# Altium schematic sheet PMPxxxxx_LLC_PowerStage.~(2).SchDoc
size 431 x 279 mm; Date: Not shown in title block; ApprovedBy: Not shown in title block; CheckedBy: Not shown in title block; Author: Not shown in title block; CompanyName: Not shown in title block; Engineer: Not shown in title block; Organization: Not shown in title block; Address1: Not shown in title block; Address2: Not shown in title block; Address3: Not shown in title block; Address4: Not shown in title block; DocumentNumber: 2; Revision: Use project parameter SCH_Rev; SheetNumber: 2; SheetTotal: 4; PageSetup: Record=PageOptions¦CenterHorizontal=True¦CenterVertical=True¦PrintScale=1.00¦XCorrection=1.00¦YCorrection=1.00¦PrintKind=0¦BorderSize=5000000¦LeftOffset=0¦BottomOffset=0¦Orientation=2¦PaperLength=1000¦PaperWidth=1000¦Scale=100¦PaperSource=15¦PrintQuality=600¦MediaType=1¦DitherType=10¦PaperKind=Letter¦PrintScaleMode=1
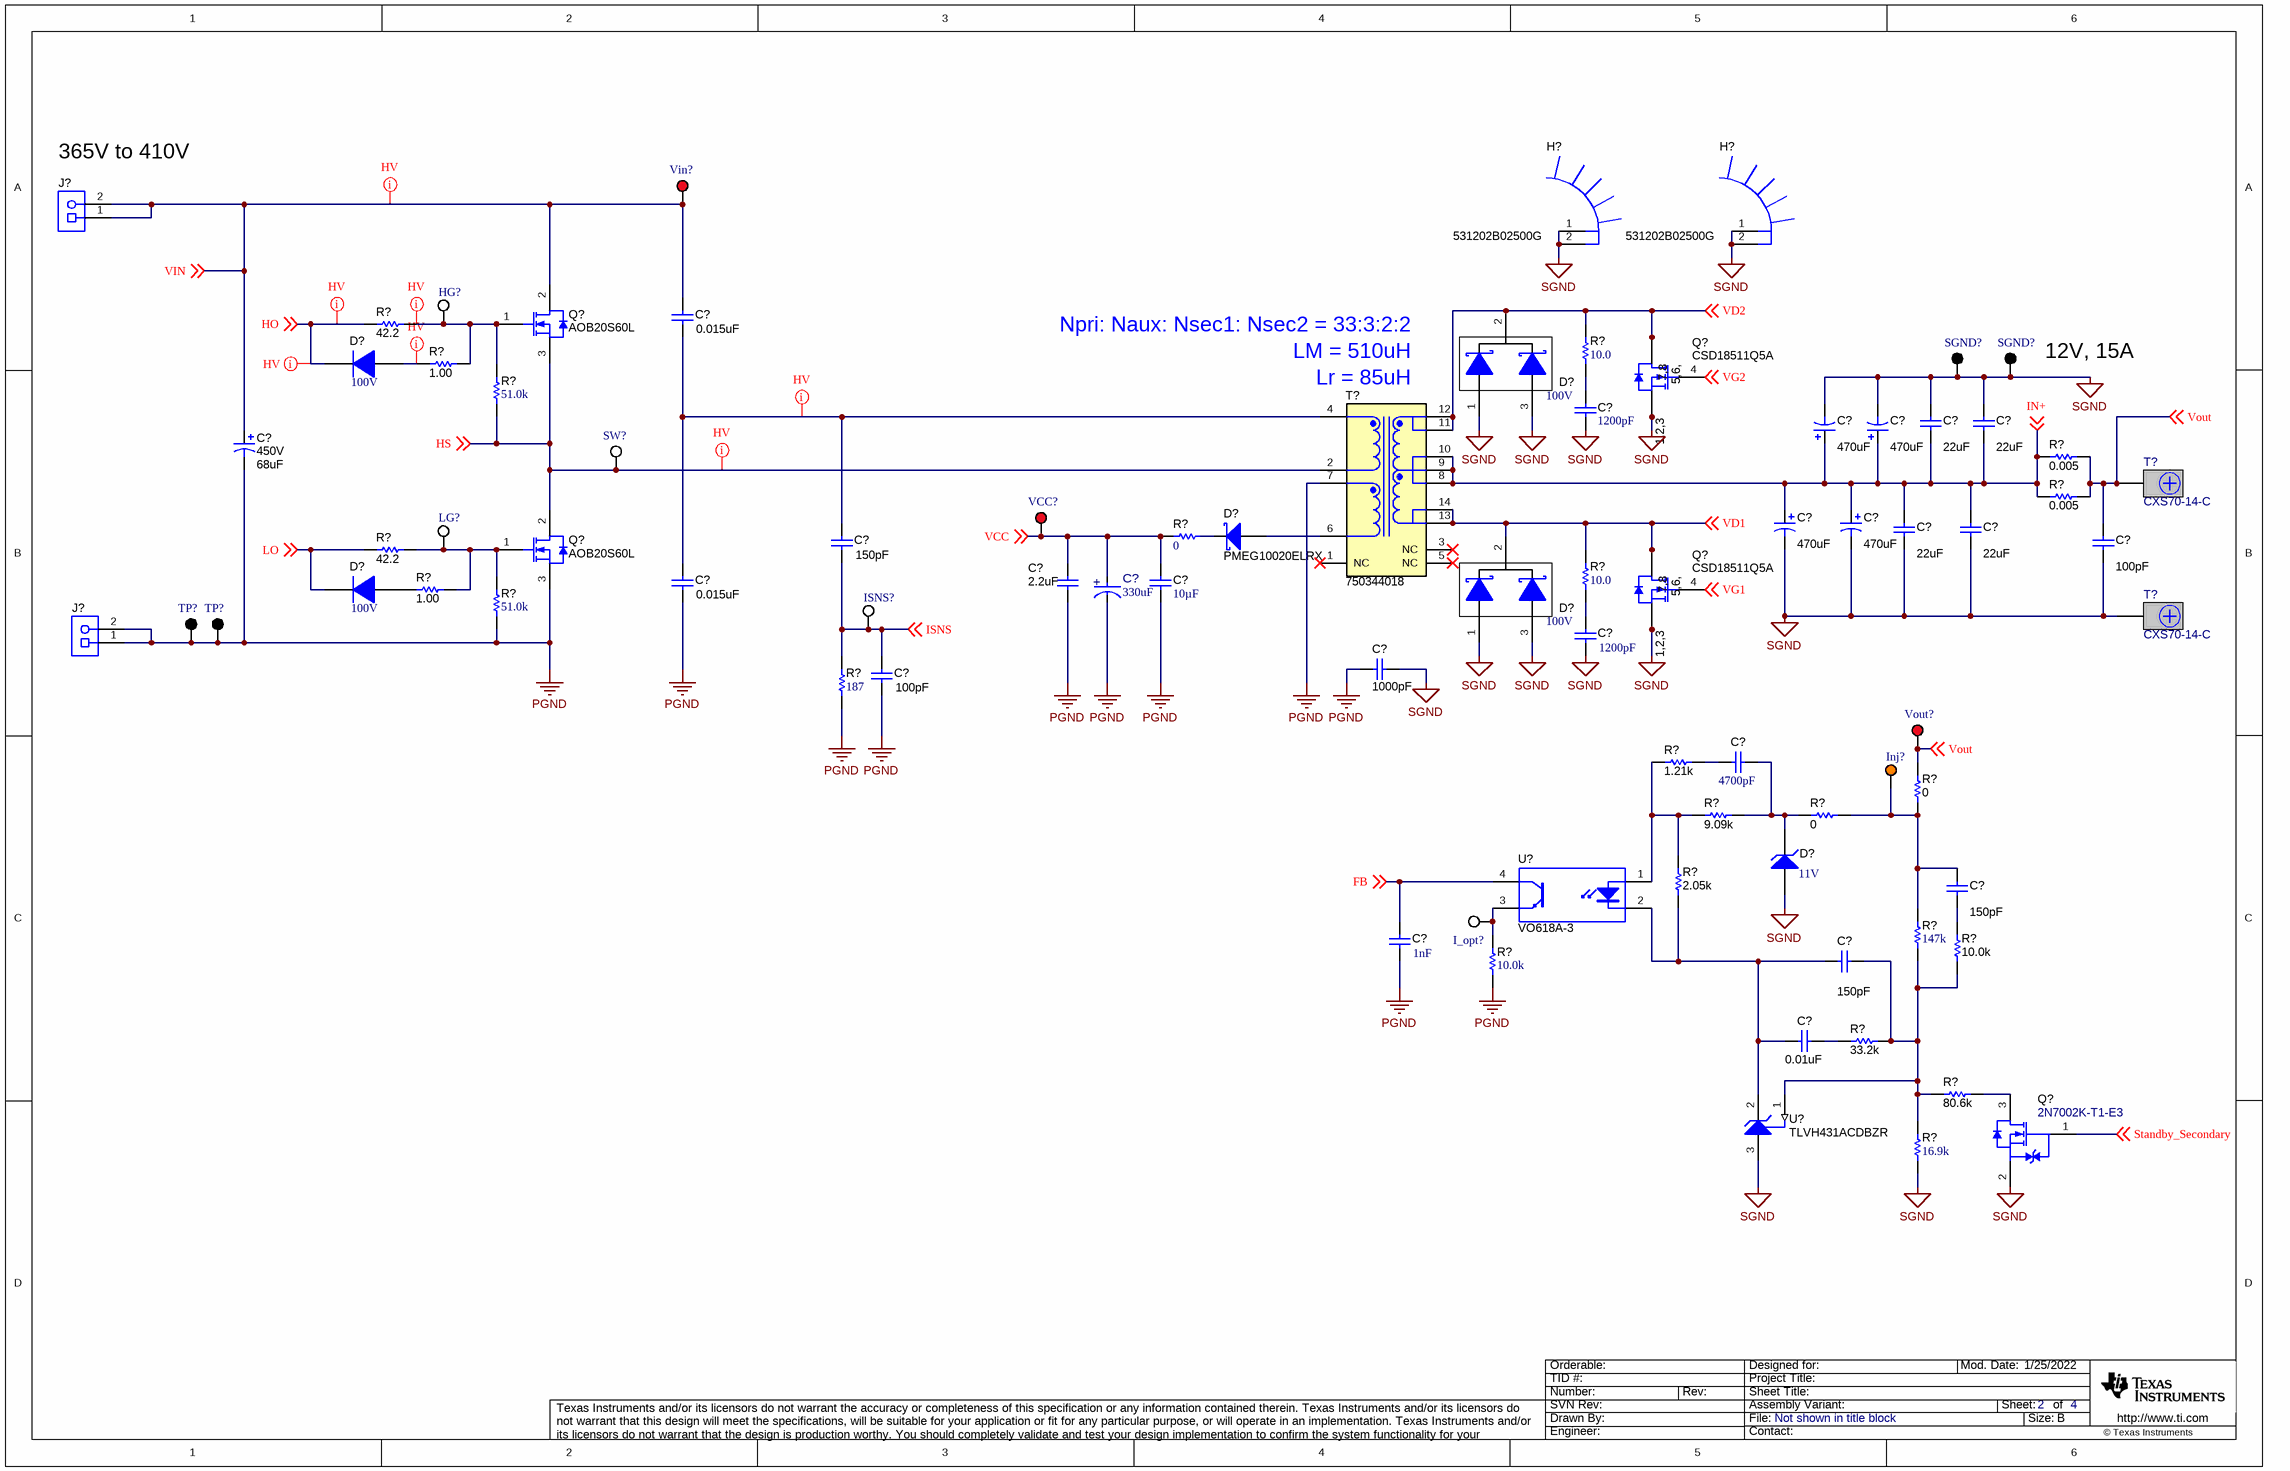
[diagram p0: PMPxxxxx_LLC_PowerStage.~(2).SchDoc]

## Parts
(Parts that share a designator on the sheet are numbered #1, #2 ... from top to bottom, then left to right.)
C?#1  ValueDisplayed: 0.015uF  [B32652_1800x700x1250]  (hidden comment: B32652A7153J000)
C?#2  ValueDisplayed: 1200pF  [0805L]  (hidden comment: GRM2165C2A122JA01D)
C?#3  ValueDisplayed: 470uF  [HW_1000x1600]  (hidden comment: UHW1V471MPD)
C?#4  ValueDisplayed: 470uF  [HW_1000x1600]  (hidden comment: UHW1V471MPD)
C?#5  ValueDisplayed: 22uF  [1206_190L]  (hidden comment: C3216X5R1E226M160AB)
C?#6  ValueDisplayed: 22uF  [1206_190L]  (hidden comment: C3216X5R1E226M160AB)
C?#7  VDC_V: 450V  ValueDisplayed: 68uF  [KXG_1800x3150]  (hidden comment: EKXG451ELL680MMN3S)
C?#8  ValueDisplayed: 470uF  [HW_1000x1600]  (hidden comment: UHW1V471MPD)
C?#9  ValueDisplayed: 470uF  [HW_1000x1600]  (hidden comment: UHW1V471MPD)
C?#10  ValueDisplayed: 22uF  [1206_190L]  (hidden comment: C3216X5R1E226M160AB)
C?#11  ValueDisplayed: 22uF  [1206_190L]  (hidden comment: C3216X5R1E226M160AB)
C?#12  ValueDisplayed: 150pF  [1206L]  (hidden comment: GRM31A5C2J151JW01D)
C?#13  ValueDisplayed: 100pF  [0603L]  (hidden comment: 06035A101FAT2A)
C?#14  ValueDisplayed: 330uF  [FP-35ZL330MEFC10X16_RADIAL-MFG]  (hidden comment: 35ZL330MEFC10X16)
C?#15  ValueDisplayed: 0.015uF  [B32652_1800x700x1250]  (hidden comment: B32652A7153J000)
C?#16  ValueDisplayed: 2.2uF  [0805L]  (hidden comment: C2012X7R1V225K085AC)
C?#17  ValueDisplayed: 10µF  [1206_180]  (hidden comment: C1206C106J3RACAUTO)
C?#18  ValueDisplayed: 1200pF  [0805L]  (hidden comment: GRM2165C2A122JA01D)
C?#19  ValueDisplayed: 1000pF  [CD45_700x600x1100]  (hidden comment: CD45-E2GA102M-NKA)
C?#20  ValueDisplayed: 100pF  [1206L]  (hidden comment: 12061A101JAT2A)
C?#21  ValueDisplayed: 4700pF  [0603L]  (hidden comment: C0603C472J1GAC7867)
C?#22  ValueDisplayed: 150pF  [0402L]  (hidden comment: 885012005062)
C?#23  Cap_F: 1nF  [1206L]  (hidden comment: 12061A102JAT2A)
C?#24  ValueDisplayed: 150pF  [0402L]  (hidden comment: 885012005062)
C?#25  ValueDisplayed: 0.01uF  [0603L]  (hidden comment: 06031C103JAT2A)
D?#1  Vr_V: 100V  [SOD-123]  (hidden comment: 1N4148W-7-F)
D?#2  Vr_V: 100V  [TO-220AB_100mil]  (hidden comment: STPS41H100CTY)
D?#3  PMEG10020ELRX  [SOD-123W]
D?#4  Vr_V: 100V  [SOD-123]  (hidden comment: 1N4148W-7-F)
D?#5  Vr_V: 100V  [TO-220AB_100mil]  (hidden comment: STPS41H100CTY)
D?#6  Vz_V: 11V  [SMA]  (hidden comment: 1SMA5926BT3G)
H?#1  531202B02500G  [531202]
H?#2  531202B02500G  [531202]
HG?  5012  [Keystone5012]  (value not drawn)
I_opt?  5012  [Keystone5012]  (value not drawn)
Inj?  5013  [Keystone5013]  (value not drawn)
ISNS?  5012  [Keystone5012]  (value not drawn)
J?#1  ED120/2DS  [On-Shore_ED120_2DS]  (value not drawn)
J?#2  ED120/2DS  [On-Shore_ED120_2DS]  (value not drawn)
LG?  5012  [Keystone5012]  (value not drawn)
Q?#1  AOB20S60L  [DDPAK]
Q?#2  CSD18511Q5A  [DQJ0008A]
Q?#3  AOB20S60L  [DDPAK]
Q?#4  CSD18511Q5A  [DQJ0008A]
Q?#5  2N7002K-T1-E3  [SOT-23L]
R?#1  ValueDisplayed: 42.2  [0603]  (hidden comment: RC0603FR-0742R2L)
R?#2  ValueDisplayed: 10.0  [1206L]  (hidden comment: RC1206FR-0710RL)
R?#3  ValueDisplayed: 1.00  [0603L]  (hidden comment: RC0603FR-071RL)
R?#4  ValueDisplayed: 51.0k  [0603L]  (hidden comment: RC0603FR-0751KL)
R?#5  ValueDisplayed: 0.005  [2010L]  (hidden comment: CSNL2010FT5L00)
R?#6  ValueDisplayed: 0.005  [2010L]  (hidden comment: CSNL2010FT5L00)
R?#7  ValueDisplayed: 0  [1206L]  (hidden comment: ERJ-8GEY0R00V)
R?#8  ValueDisplayed: 42.2  [0603L]  (hidden comment: RC0603FR-0742R2L)
R?#9  ValueDisplayed: 10.0  [1206L]  (hidden comment: RC1206FR-0710RL)
R?#10  ValueDisplayed: 1.00  [0603L]  (hidden comment: RC0603FR-071RL)
R?#11  ValueDisplayed: 51.0k  [0603L]  (hidden comment: RC0603FR-0751KL)
R?#12  ValueDisplayed: 187  [1206]  (hidden comment: RC1206FR-07187RL)
R?#13  ValueDisplayed: 1.21k  [0603L]  (hidden comment: RC0603FR-071K21L)
R?#14  ValueDisplayed: 0  [0402L]  (hidden comment: RC0402JR-070RL)
R?#15  ValueDisplayed: 9.09k  [0603L]  (hidden comment: RC0603FR-079K09L)
R?#16  ValueDisplayed: 0  [1206L]  (hidden comment: CRCW12060000Z0EAHP)
R?#17  ValueDisplayed: 2.05k  [0603L]  (hidden comment: RC0603FR-072K05L)
R?#18  ValueDisplayed: 147k  [0603L]  (hidden comment: RC0603FR-07147KL)
R?#19  ValueDisplayed: 10.0k  [0603L]  (hidden comment: ERJ-3EKF1002V)
R?#20  ValueDisplayed: 10.0k  [0402L]  (hidden comment: ERJ-2RKF1002X)
R?#21  ValueDisplayed: 33.2k  [0603L]  (hidden comment: RC0603FR-0733K2L)
R?#22  ValueDisplayed: 80.6k  [0603L]  (hidden comment: RC0603FR-0780K6L)
R?#23  ValueDisplayed: 16.9k  [0603L]  (hidden comment: RC0603FR-0716K9L)
SGND?#1  5011  [Keystone5011]  (value not drawn)
SGND?#2  5011  [Keystone5011]  (value not drawn)
SW?  5012  [Keystone5012]  (value not drawn)
T?#1  750344018  [Wurth_750344018]
T?#2  CXS70-14-C  [Panduit_CXS70-14-C]
T?#3  CXS70-14-C  [Panduit_CXS70-14-C]
TP?#1  5011  [Keystone5011]  (value not drawn)
TP?#2  5011  [Keystone5011]  (value not drawn)
U?#1  VO618A-3  [DIP-4]
U?#2  TLVH431ACDBZR  [DBZ0003A_N]
VCC?  5010  [Keystone5010]  (value not drawn)
Vin?  5010  [Keystone5010]  (value not drawn)
Vout?  5010  [Keystone5010]  (value not drawn)

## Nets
PGND: C?#7.2(-) C?#14.1(CATHODE) C?#15.2 C?#16.2 C?#17.2 C?#19.2 C?#20.2 C?#23.2 J?#2.1 J?#2.2 Q?#3.3(S) R?#11.1 R?#12.1 R?#20.1 T?#1.7 TP?#1.1 TP?#2.1
SGND: C?#2.2 C?#3.2(-) C?#4.2(-) C?#5.1 C?#6.1 C?#8.2(-) C?#9.2(-) C?#10.2 C?#11.2 C?#13.2 C?#18.2 C?#19.1 D?#2.1(A) D?#2.3(A) D?#5.1(A) D?#5.3(A) D?#6.2(A) H?#1.1 H?#1.2 H?#2.1 H?#2.2 Q?#2.1(S) Q?#2.2(S) Q?#2.3(S) Q?#4.1(S) Q?#4.2(S) Q?#4.3(S) Q?#5.2(S) R?#23.1 SGND?#1.1 SGND?#2.1 T?#3.1 U?#2.3(ANODE)
FB: C?#23.1 U?#1.4(C) ; off-sheet FB
HO: D?#1.1(K) R?#1.1 ; off-sheet HO
HS: Q?#1.3(S) Q?#3.2(D) R?#4.1 SW?.1 T?#1.2 ; off-sheet HS
IN+: C?#3.1(+) C?#4.1(+) C?#5.2 C?#6.2 C?#8.1(+) C?#9.1(+) C?#10.1 C?#11.1 R?#5.1 R?#6.1 T?#1.8 T?#1.9 T?#1.10 ; off-sheet IN+
ISNS: C?#12.2 C?#20.1 ISNS?.1 R?#12.2 ; off-sheet ISNS
LO: D?#4.1(K) R?#8.1 ; off-sheet LO
Standby_Secondary: Q?#5.1(G) ; off-sheet Standby_Secondary
VCC: C?#14.2(ANODE) C?#16.1 C?#17.1 R?#7.1 VCC?.1 ; off-sheet VCC
VD1: D?#5.2(K) Q?#4.5(D) Q?#4.6(D) Q?#4.7(D) Q?#4.8(D) Q?#4.9(D) R?#9.2 T?#1.13 T?#1.14 ; off-sheet VD1
VD2: D?#2.2(K) Q?#2.5(D) Q?#2.6(D) Q?#2.7(D) Q?#2.8(D) Q?#2.9(D) R?#2.2 T?#1.11 T?#1.12 ; off-sheet VD2
VG1: Q?#4.4(G) ; off-sheet VG1
VG2: Q?#2.4(G) ; off-sheet VG2
VIN: C?#1.1 C?#7.1(+) J?#1.1 J?#1.2 Q?#1.2(D) Vin?.1 ; off-sheet VIN
Vout: C?#13.1 R?#5.2 R?#6.2 R?#14.2 T?#2.1 Vout?.1 ; off-sheet Vout
NetC?#1_2: C?#1.2 C?#12.1 C?#15.1 T?#1.4
NetC?#2_1: C?#2.1 R?#2.1
NetC?#18_1: C?#18.1 R?#9.1
NetC?#21_1: C?#21.1 D?#6.1(K) R?#15.2 R?#16.1
NetC?#21_2: C?#21.2 R?#13.2
NetC?#22_1: C?#22.1 Inj?.1 R?#14.1 R?#16.2 R?#18.2
NetC?#22_2: C?#22.2 R?#19.2
NetC?#24_1: C?#24.1 R?#18.1 R?#19.1 R?#21.1 R?#22.1 R?#23.2 U?#2.1(REF)
NetC?#24_2: C?#24.2 C?#25.2 R?#17.1 U?#1.2(K) U?#2.2(CATHODE)
NetC?#25_1: C?#25.1 R?#21.2
NetD?#1_2: D?#1.2(A) R?#3.1
NetD?#3_1: D?#3.1(K) R?#7.2
NetD?#3_2: D?#3.2(A) T?#1.6
NetD?#4_2: D?#4.2(A) R?#10.1
NetHG?_1: HG?.1 Q?#1.1(G) R?#1.2 R?#3.2 R?#4.2
NetI_opt?_1: I_opt?.1 R?#20.2 U?#1.3(E)
NetLG?_1: LG?.1 Q?#3.1(G) R?#8.2 R?#10.2 R?#11.2
NetQ?#5_3: Q?#5.3(D) R?#22.2
NetR?#13_1: R?#13.1 R?#15.1 R?#17.2 U?#1.1(A)

Not connected (* = marked no-connect by the designer): T?#1 1(NC)* 3(NC)* 5(NC)*

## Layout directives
net class HV: HO, HS, NetC?#1_2, NetD?#1_2, NetHG?_1, VIN

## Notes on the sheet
- (near J?#1) 365V to 410V
- LM = 510uH
- Npri: Naux: Nsec1: Nsec2 = 33:3:2:2
- (near SGND?#2) 12V, 15A
- (near T?#1) Lr = 85uH

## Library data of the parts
C?#1 C?#15 = CMP-0012346-3: CAP, Film, 0.015 uF, 1250 V, +/- 5%, AEC-Q200 Grade 3, TH; Manufacturer: TDK; TaMin_C: -55°C; Polarized: N; SizeAreaWB_mm2: 180; Value1: Unknown; TaMax_C: 100°C; SizeZ_mm: 12.5; SizeX_mm: 18; SizeY_mm: 7; Cap_Case: 18x7x12.5; Value2: 1250V; SizeArea_mm2: 126; CompType: Capacitor; AEC Qualified: Y; Cap_F: 15nF; VDC_V: 1.25kV; AEC Grade: 3; AEC Category: Q200
C?#2 C?#18 = CMP-0008098-2: CAP, CERM, 1200 pF, 100 V, +/- 5%, C0G/NP0, 0805; Manufacturer: MuRata; TaMin_C: -55°C; Polarized: N; SizeAreaWB_mm2: 6.75; Value1: Unknown; U/M: EA; Value: 1200pF; TaMax_C: 125°C; SizeZ_mm: 1.45; SizeX_mm: 2; SizeY_mm: 1.25; Cap_Case: 0805; Value2: 100V; SizeArea_mm2: 2.5; Cap_F: 1.2nF; AEC Category: Q200
C?#3 C?#4 C?#8 C?#9 = CMP-0010541-2: CAP, AL, 470 uF, 35 V, +/- 20%, 0.03 ohm, TH; Manufacturer: Nichicon; TaMin_C: -40°C; ESR_ohm: 0.03; Polarized: Y; SizeAreaWB_mm2: 144; U/M: EA; Value: 470uF; TaMax_C: 105°C; SizeZ_mm: 17.5; SizeX_mm: 10; Cap_Case: 10x16mm; Value2: 35V; SizeArea_mm2: 100; CompType: Capacitor; AEC Qualified: N; Cap_F: 470µF; IRMS_A: 2A; AEC Category: Q200
C?#5 C?#6 C?#10 C?#11 = CMP-0008654-2: CAP, CERM, 22 uF, 25 V, +/- 20%, X5R, 1206_190; Manufacturer: TDK; TaMin_C: -55°C; Polarized: N; SizeAreaWB_mm2: 10.92; Value1: Unknown; U/M: EA; Value: 22uF; TaMax_C: 85°C; SizeZ_mm: 1.9; SizeX_mm: 3.2; SizeY_mm: 1.6; Cap_Case: 1206; Value2: 25V; SizeArea_mm2: 5.12; CompType: Capacitor; Cap_F: 22µF; AEC Category: Q200
C?#7 = CMP-0010043-2: CAP, AL, 68 uF, 450 V, +/- 20%, TH; Manufacturer: Chemi-Con; TaMin_C: -25°C; Polarized: Y; SizeAreaWB_mm2: 400; Value1: Unknown; U/M: EA; Value: 68uF; TaMax_C: 105°C; SizeZ_mm: 33; SizeX_mm: 18; Cap_Case: 18x31.5mm; SizeArea_mm2: 324; CompType: Capacitor; Cap_F: 68µF; IRMS_A: 6.3dA; AEC Category: Q200
C?#12 = CMP-0008885-2: CAP, CERM, 150 pF, 630 V, +/- 5%, C0G/NP0, 1206; Manufacturer: MuRata; TaMin_C: -55°C; Polarized: N; SizeAreaWB_mm2: 10.92; Value1: Unknown; U/M: EA; Value: 150pF; TaMax_C: 125°C; SizeZ_mm: 1.35; SizeX_mm: 3.2; SizeY_mm: 1.6; Cap_Case: 1206; Value2: 630V; SizeArea_mm2: 5.12; CompType: Capacitor; AEC Category: Q200
C?#13 = CMP-0006762-4: CAP, CERM, 100 pF, 50 V, +/- 1%, C0G/NP0, 0603; Manufacturer: AVX; TaMin_C: -55°C; Polarized: N; SizeAreaWB_mm2: 4.68; Value1: Unknown; U/M: EA; TaMax_C: 125°C; SizeZ_mm: 1; SizeX_mm: 1.6; SizeY_mm: 0.8; Cap_Case: 0603; Value2: 50V; SizeArea_mm2: 1.28; CompType: Capacitor; Value: 100pF; AEC Category: Q200
C?#14 = CMP-0098283-1: Cap Aluminum Lytic 330uF 35V 20% (10 X 16mm) Radial 5mm 1430mA 4000h 105C Bulk; Manufacturer: Rubycon; AEC Qualified: No; Cap_F: 330µF; IRMS_A: 1.43A; SizeZ_mm: 17.5mm; Dissipation Factor: 12%; Leakage Current: 115.5uA; Life: 4000Hours; Value: 330µF
C?#16 = CMP-0007883-2: CAP, CERM, 2.2 uF, 35 V, +/- 10%, X7R, 0805; Manufacturer: TDK; TaMin_C: -55°C; Polarized: N; SizeAreaWB_mm2: 6.75; Value1: Unknown; U/M: EA; Value: 2.2uF; TaMax_C: 125°C; SizeZ_mm: 1.45; SizeX_mm: 2; SizeY_mm: 1.25; Cap_Case: 0805; Value2: 35V; SizeArea_mm2: 2.5; CompType: Capacitor; Cap_F: 2.2µF; AEC Category: Q200
C?#17 = CMP-0081062-1: CAP, CERM, 10 µF, 25 V,+/- 5%, X7R, AEC-Q200 Grade 1, 1206; Manufacturer: Kemet; TaMin_C: -55°C; Polarized: N; SizeAreaWB_mm2: 10.92; U/M: EA; Value: 10uF; TaMax_C: 125°C; SizeZ_mm: 1.8; SizeX_mm: 3.2; SizeY_mm: 1.6; Value2: 25V; SizeArea_mm2: 5.12; AEC Qualified: Y; AEC Grade: 1; AEC Category: Q200
C?#19 = CMP-0009595-2: CAP, CERM, 1000 pF,  V, +/- 20%, E, D7xT6mm; Manufacturer: TDK; TaMin_C: -25°C; Polarized: N; SizeAreaWB_mm2: 101.2; Value1: Unknown; U/M: EA; Value: 1000pF; TaMax_C: 125°C; SizeZ_mm: 11; SizeX_mm: 10.65; SizeY_mm: 6; Cap_Case: 7x6x11mm; SizeArea_mm2: 63.9; Cap_F: 1nF; AEC Category: Q200
C?#20 = CMP-0008462-2: CAP, CERM, 100 pF, 100 V, +/- 5%, C0G/NP0, 1206; Manufacturer: AVX; TaMin_C: -55°C; ESR_ohm: 7.01d; Polarized: N; SizeAreaWB_mm2: 10.92; Value1: 0.701 ohm; U/M: EA; Value: 100pF; TaMax_C: 125°C; SizeZ_mm: 1.35; SizeX_mm: 3.2; SizeY_mm: 1.6; Cap_Case: 1206; Value2: 100V; SizeArea_mm2: 5.12; CompType: Capacitor; AEC Category: Q200
C?#21 = CMP-0006941-4: CAP, CERM, 4700 pF, 100 V, +/- 5%, C0G/NP0, 0603; Manufacturer: Kemet; TaMin_C: -55°C; Polarized: N; SizeAreaWB_mm2: 4.68; Value1: Unknown; U/M: EA; Value: 4700pF; TaMax_C: 125°C; SizeZ_mm: 1; SizeX_mm: 1.6; SizeY_mm: 0.8; Cap_Case: 0603; Value2: 100V; SizeArea_mm2: 1.28; Cap_F: 4.7nF; AEC Category: Q200
C?#22 C?#24 = CMP-0064913-2: CAP, CERM, 150 pF, 50 V,+/- 5%, C0G/NP0, 0402; Manufacturer: Wurth Elektronik; TaMin_C: -55°C; Polarized: N; SizeAreaWB_mm2: 3; Value1: Unknown; U/M: EA; Value: 150pF; TaMax_C: 125°C; SizeZ_mm: 0.6; SizeX_mm: 1; SizeY_mm: 0.5; Cap_Case: 0402; Value2: 50V; CompType: Capacitor; AEC Category: Q200
C?#23 = CMP-0008465-2: CAP, CERM, 1000 pF, 100 V, +/- 5%, C0G/NP0, 1206; Manufacturer: AVX; TaMin_C: -55°C; ESR_ohm: 2.38d; Polarized: N; SizeAreaWB_mm2: 10.92; Value1: 0.238 ohm; U/M: EA; Value: 1000pF; TaMax_C: 125°C; SizeZ_mm: 1.35; SizeX_mm: 3.2; SizeY_mm: 1.6; Cap_Case: 1206; Value2: 100V; SizeArea_mm2: 5.12; AEC Category: Q200
C?#25 = CMP-0006726-4: CAP, CERM, 0.01 uF, 100 V, +/- 5%, X7R, 0603; Manufacturer: AVX; TaMin_C: -55°C; ESR_ohm: 0.098; Polarized: N; SizeAreaWB_mm2: 4.68; Value1: 0.098 ohm; U/M: EA; Value: 0.01uF; TaMax_C: 125°C; SizeZ_mm: 1; SizeX_mm: 1.6; SizeY_mm: 0.8; Cap_Case: 0603; Value2: 100V; SizeArea_mm2: 1.28; Cap_F: 10nF; AEC Category: Q200
D?#1 D?#4 = CMP-0029001-2: Diode, Ultrafast, 100 V, 0.15 A, SOD-123; Manufacturer: Diodes Inc.; Io_A: 150mA; Green_Lifecycle: Active; SizeAreaWB_mm2: 13.095; Green_REACh: Passed; Value1: 0.15A; TJmax_C: 150°C; Value: 100V; SizeZ_mm: 1.35; SizeX_mm: 3.85; SizeY_mm: 1.7; Vf_V: 1.25V; SizeArea_mm2: 6.545; AEC Category: Q101
D?#2 D?#5 = CMP-0028866-3: Diode, Schottky, 100 V, 20 A, AEC-Q101, TH; Manufacturer: STMicroelectronics; Io_A: 20A; Green_Lifecycle: Not Set; SizeAreaWB_mm2: 79.3; Green_REACh: Incomplete; TJmax_C: 175°C; Value: 100V; SizeZ_mm: 19.4; SizeX_mm: 10.2; SizeY_mm: 4.5; Vf_V: 800mV; Value2: 0.8V; SizeArea_mm2: 45.9; AEC Qualified: Y; AEC Category: Q101
D?#3 = CMP-0028977-2: Diode, Schottky, 100 V, 2 A, AEC-Q101, SOD-123W; Manufacturer: Nexperia; Io_A: 2A; SizeAreaWB_mm2: 12.15; Vr_V: 100V; TJmax_C: 175°C; Value: 100V; SizeZ_mm: 1; SizeX_mm: 3.5; SizeY_mm: 1.7; Vf_V: 830mV; Value2: 0.83V; SizeArea_mm2: 5.95; AEC Qualified: Y; AEC Category: Q101
D?#6 = CMP-0005522-4: Diode, Zener, 11 V, 1.5 W, SMA; Manufacturer: ON Semiconductor; Power_W: 1.5W; SizeAreaWB_mm2: 37.3428; RJA_CperW: 250; Value: 11V; SizeZ_mm: 2.87; SizeX_mm: 5.59; SizeY_mm: 2.92; SizeArea_mm2: 16.3228; AEC Category: Q101
H?#1 H?#2 = CMP-0004053-1: Manufacturer: Aavid; Note: footprint renamed from HSINK_531202B025B025 to 531202; CompType: Heat Sink
HG? I_opt? ISNS? LG? SW? = CMP-0055149-2: Test Point, Multipurpose, White, TH; Manufacturer: Keystone Electronics; CNHeader: FALSE; Green_Lifecycle: Active; Green_REACh: Passed; ContactFinish: Silver; CT: TRUE
Inj? = CMP-0055150-2: Test Point, Multipurpose, Orange, TH; Manufacturer: Keystone Electronics; CNHeader: FALSE; Green_Lifecycle: Active; Green_REACh: Passed; ContactFinish: Silver; CT: TRUE
J?#1 J?#2 = CMP-0074910-1: Terminal Block, 5.08 mm, 2x1, Brass, TH; Manufacturer: On-Shore Technology; Cert_VDE: Y; CNHeader: False; Current_A: 15A; Green_Lifecycle: Not Set; Shrouded: N; Gender: Female; Green_REACh: Incomplete; Voltage_V: 300V; Row_Count: 1; Pitch_mm: 5.08; CT: True
Q?#1 Q?#3 = CMP-0001135-4: MOSFET, N-CH, 600 V, 20 A, DDPAK; Alternate Manufacturer: None; Manufacturer: AOS; SizeZ_mm: 4.445; ChType: N; Value2: 19.8 nC; VdsMax_V: 600V; SizeX_mm: 15.245; SizeAreaWB_mm2: 209.6992; SizeY_mm: 10.16; Vgs_V: 30V; QgTyp_nC: 19.8; Value: 600V; SizeArea_mm2: 154.8892; AEC Category: Q101; IdsMax_A: 20A; ChMode: Enhancement
Q?#2 Q?#4 = CMP-0000711-1: MOSFET, N-CH, 40 V, 100 A, DQJ0008A (VSONP-8); Alternate Manufacturer: None; Manufacturer: Texas Instruments; SizeZ_mm: 1.1; ChType: N; Value2: 63 nC; Value1: 0.003; VdsMax_V: 40V; SizeX_mm: 6; SizeY_mm: 4.9; Vgs_V: 20V; Value: 40V; Rdson45_ohm: 3.5m; SizeArea_mm2: 29.4; AEC Category: Q101; IdsMax_A: 100A; SizeAreaWB_mm2: 55.2; U/M: EA; QgTyp_nC: 63
Q?#5 = CMP-0000773-1: MOSFET, N-CH, 60 V, 0.3 A, SOT-23; Alternate Manufacturer: None; Manufacturer: Vishay-Siliconix; SizeZ_mm: 1.1; ChType: N; Value2: 0.4 nC; VdsMax_V: 60V; SizeX_mm: 2.5; SizeY_mm: 3; Vgs_V: 20V; Value: 60V; Rdson45_ohm: 4; SizeArea_mm2: 7.5; AEC Category: Q101; IdsMax_A: 300mA; SizeAreaWB_mm2: 14; U/M: EA; QgTyp_nC: 0.4
R?#1 R?#8 = CMP-0023107-5: RES, 42.2, 1%, 0.1 W, 0603; Manufacturer: Yageo; Power_W: 100mW; TempCo: 100 ppm/C; Value_Code: 42R2; Value: 42.2; EIA_Code: E96; SizeX_mm: 1.6; SizeY_mm: 0.8; SizeZ_mm: 1; Value2: 0.1W; SizeArea_mm2: 1.28; CompType: Resistor; AEC Qualified: N; VDC_V: 75V; AEC Category: Q200; SizeAreaWB_mm2: 4.68
R?#2 R?#9 = CMP-0017851-2: RES, 10.0, 1%, 0.25 W, 1206; Manufacturer: Yageo America; Power_W: 250mW; TempCo: 200 ppm/C; Value_Code: 10R0; U/M: EA; Value: 10.0; EIA_Code: E96; Res_ohm: 10; SizeX_mm: 3.2; SizeY_mm: 1.6; SizeZ_mm: 1.35; Value2: 0.25W; SizeArea_mm2: 5.12; VDC_V: 200V; AEC Category: Q200
R?#3 R?#10 = CMP-0022900-4: RES, 1.00, 1%, 0.1 W, 0603; Manufacturer: Yageo; Power_W: 100mW; TempCo: 200 ppm/C; Value_Code: 1R00; Value: 1.00; EIA_Code: E96; Res_ohm: 1; SizeX_mm: 1.6; SizeY_mm: 0.8; Value2: 0.1W; SizeArea_mm2: 1.28; CompType: Resistor; AEC Qualified: N; VDC_V: 75V; AEC Category: Q200; SizeAreaWB_mm2: 4.68
R?#4 R?#11 = CMP-0023167-5: RES, 51.0 k, 1%, 0.1 W, 0603; Manufacturer: Yageo; Power_W: 100mW; TempCo: 100 ppm/C; Value_Code: 51k0; Value: 51.0k; Res_ohm: 51k; SizeX_mm: 1.6; SizeY_mm: 0.8; SizeZ_mm: 1; Value2: 0.1W; SizeArea_mm2: 1.28; AEC Qualified: N; VDC_V: 75V; AEC Category: Q200; SizeAreaWB_mm2: 4.68
R?#5 R?#6 = CMP-0016512-2: RES, 0.005, 1%, 1.5 W, 2010; Manufacturer: Stackpole Electronics Inc; Power_W: 1.5W; TempCo: 50 ppm/C; Value_Code: 5L000; U/M: EA; Value: 0.005; EIA_Code: E96; Res_ohm: 5m; SizeX_mm: 5; SizeY_mm: 2.5; SizeZ_mm: 1.66; SizeArea_mm2: 12.5; CompType: Resistor; AEC Category: Q200
R?#7 = CMP-0018748-3: RES, 0, 5%, 0.25 W, AEC-Q200 Grade 0, 1206; Manufacturer: Panasonic; Power_W: 250mW; TempCo: 600 ppm/C; Value_Code: 0000; Value: 0; EIA_Code: E24; SizeX_mm: 3.2; SizeY_mm: 1.6; SizeZ_mm: 1.35; Value2: 0.25W; SizeArea_mm2: 5.12; AEC Qualified: Y; VDC_V: 200V; AEC Category: Q200; SizeAreaWB_mm2: 10.92
R?#12 = CMP-0017949-2: RES, 187, 1%, 0.25 W, 1206; Manufacturer: Yageo America; Power_W: 250mW; TempCo: 100 ppm/C; Value_Code: 187R; U/M: EA; Value: 187; EIA_Code: E96; SizeX_mm: 3.2; SizeY_mm: 1.6; SizeZ_mm: 1.35; Value2: 0.25W; SizeArea_mm2: 5.12; VDC_V: 200V; AEC Category: Q200
R?#13 = CMP-0022871-5: RES, 1.21 k, 1%, 0.1 W, 0603; Manufacturer: Yageo; Power_W: 100mW; TempCo: 100 ppm/C; Value_Code: 1k21; Value: 1.21k; EIA_Code: E96; SizeX_mm: 1.6; SizeY_mm: 0.8; SizeZ_mm: 1; Value2: 0.1W; SizeArea_mm2: 1.28; AEC Qualified: N; VDC_V: 75V; AEC Category: Q200; SizeAreaWB_mm2: 4.68
R?#14 = CMP-0027004-2: RES, 0, 5%, 0.063 W, 0402; Manufacturer: Yageo America; Power_W: 63mW; TempCo: 200 ppm/C; Value_Code: 0000; U/M: EA; Value: 0; EIA_Code: E24; SizeX_mm: 1; SizeY_mm: 0.5; SizeZ_mm: 0.6; Value2: 0.063W; CompType: Resistor; VDC_V: 50V; AEC Category: Q200
R?#15 = CMP-0023332-5: RES, 9.09 k, 1%, 0.1 W, 0603; Manufacturer: Yageo; Power_W: 100mW; TempCo: 100 ppm/C; Value_Code: 9k09; Value: 9.09k; EIA_Code: E96; SizeX_mm: 1.6; SizeY_mm: 0.8; SizeZ_mm: 1; Value2: 0.1W; SizeArea_mm2: 1.28; AEC Qualified: N; VDC_V: 75V; AEC Category: Q200; SizeAreaWB_mm2: 4.68
R?#16 = CMP-0086176-1: RES, 0, 0.75 W, AEC-Q200 Grade 0, 1206; Manufacturer: Vishay-Dale; Value: 0; SizeY_mm: 1.6; SizeX_mm: 3.2; Tolerance_%: 0%; SizeArea_mm2: 5.12; EIA_Code: E96; SizeAreaWB_mm2: 10.92; Power_W: 750mW; AEC Qualified: Y; SizeZ_mm: 1.35; Value2: 0.75W; AEC Category: Q200; VDC_V: 200V
R?#17 = CMP-0022981-5: RES, 2.05 k, 1%, 0.1 W, 0603; Manufacturer: Yageo; Power_W: 100mW; TempCo: 100 ppm/C; Value_Code: 2k05; Value: 2.05k; EIA_Code: E96; SizeX_mm: 1.6; SizeY_mm: 0.8; SizeZ_mm: 1; Value2: 0.1W; SizeArea_mm2: 1.28; AEC Qualified: N; VDC_V: 75V; AEC Category: Q200; SizeAreaWB_mm2: 4.68
R?#18 = CMP-0022800-4: RES, 147 k, 1%, 0.1 W, 0603; Manufacturer: Yageo; Power_W: 100mW; TempCo: 100 ppm/C; Value: 147k; EIA_Code: E96; SizeX_mm: 1.6; SizeY_mm: 0.8; SizeZ_mm: 1; Value2: 0.1W; SizeArea_mm2: 1.28; AEC Qualified: N; VDC_V: 75V; AEC Category: Q200; SizeAreaWB_mm2: 4.68
R?#19 = CMP-0022684-3: RES, 10.0 k, 1%, 0.1 W, 0603; Manufacturer: Panasonic; Power_W: 100mW; TempCo: 100 ppm/C; Value_Code: 10k0; U/M: EA; Value: 10.0k; EIA_Code: E96; Res_ohm: 10k; SizeX_mm: 1.6; SizeY_mm: 0.8; SizeZ_mm: 1; Value2: 0.1W; SizeArea_mm2: 1.28; CompType: Resistor; VDC_V: 75V; AEC Category: Q200
R?#20 = CMP-0026658-1: RES, 10.0 k, 1%, 0.1 W, 0402; Manufacturer: Panasonic; Power_W: 100mW; TempCo: 100 ppm/C; Value_Code: 10k0; U/M: EA; Value: 10.0k; EIA_Code: E96; Res_ohm: 10k; SizeX_mm: 1; SizeY_mm: 0.5; SizeZ_mm: 0.6; Value2: 0.1W; VDC_V: 50V; AEC Category: Q200
R?#21 = CMP-0023036-5: RES, 33.2 k, 1%, 0.1 W, 0603; Manufacturer: Yageo; Power_W: 100mW; TempCo: 100 ppm/C; Value_Code: 33k2; Value: 33.2k; EIA_Code: E96; SizeX_mm: 1.6; SizeY_mm: 0.8; SizeZ_mm: 1; Value2: 0.1W; SizeArea_mm2: 1.28; AEC Qualified: N; VDC_V: 75V; AEC Category: Q200; SizeAreaWB_mm2: 4.68
R?#22 = CMP-0023285-5: RES, 80.6 k, 1%, 0.1 W, 0603; Manufacturer: Yageo; Power_W: 100mW; TempCo: 100 ppm/C; Value_Code: 80k6; EIA_Code: E96; SizeX_mm: 1.6; SizeY_mm: 0.8; SizeZ_mm: 1; Value2: 0.1W; Value: 80.6k; SizeArea_mm2: 1.28; AEC Qualified: N; VDC_V: 75V; AEC Category: Q200; SizeAreaWB_mm2: 4.68
R?#23 = CMP-0022830-5: RES, 16.9 k, 1%, 0.1 W, 0603; Manufacturer: Yageo; Power_W: 100mW; TempCo: 100 ppm/C; Value_Code: 16k9; Value: 16.9k; EIA_Code: E96; SizeX_mm: 1.6; SizeY_mm: 0.8; SizeZ_mm: 1; Value2: 0.1W; SizeArea_mm2: 1.28; AEC Qualified: N; VDC_V: 75V; AEC Category: Q200; SizeAreaWB_mm2: 4.68
SGND?#1 SGND?#2 TP?#1 TP?#2 = CMP-0055148-2: Test Point, Multipurpose, Black, TH; Manufacturer: Keystone Electronics; CNHeader: FALSE; Green_Lifecycle: Active; Green_REACh: Passed; ContactFinish: Silver; CT: TRUE
T?#1 = CMP-0081993-1: Transformer, 510 uH, TH; Manufacturer: Wurth Elektronik; SizeAreaWB_mm2: 1732.5; SizeArea_mm2: 1569.5; AEC Qualified: N; Ns2toNp: 0.06; Lp: 510; AEC Category: Q200; Value: 510uH; SizeZ_mm: 26.5; Ind_H: 510µH; SizeY_mm: 43; LeakageInd_H: 85µH; SizeX_mm: 36.5
T?#2 T?#3 = CMP-0075010-2: Terminal 70A Lug; Manufacturer: Panduit; CNHeader: False; Green_Lifecycle: Not Set; Green_REACh: Incomplete; CompType: Screw Terminal
U?#1 = CMP-0083653-1: Optocoupler, 5.3 kV, 100-200% CTR, SMT; Manufacturer: Vishay-Semiconductor; CTR (Max): 200%; SizeAreaWB_mm2: 71.064; CTR (Min): 100%; SizeZ_mm: 5; SizeX_mm: 8.8; SizeY_mm: 4.58; SizeArea_mm2: 40.304; Voltage_Isolation_Vrms: 5.3kV
U?#2 = CMP-0033066-1: Low-Voltage Adjustable Precision Shunt Regulator, 129 ppm / degC, 80 mA, 0 to 70 degC, 3-pin SOT-23 (DBZ), Green (RoHS & no Sb/Br); Manufacturer: Texas Instruments; Min Iz for Regulation(uA): 80; VO Adj(Max)(V): 18; VO Adj(Min)(V): 1.24; Rating: Catalog; SubFamily: Shunt Voltage Reference; Temp Coeff(Max)(ppm/ degree C): 129
VCC? Vin? Vout? = CMP-0055147-2: Test Point, Multipurpose, Red, TH; Manufacturer: Keystone Electronics; CNHeader: FALSE; Green_Lifecycle: Active; Green_REACh: Passed; ContactFinish: Silver; CT: TRUE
